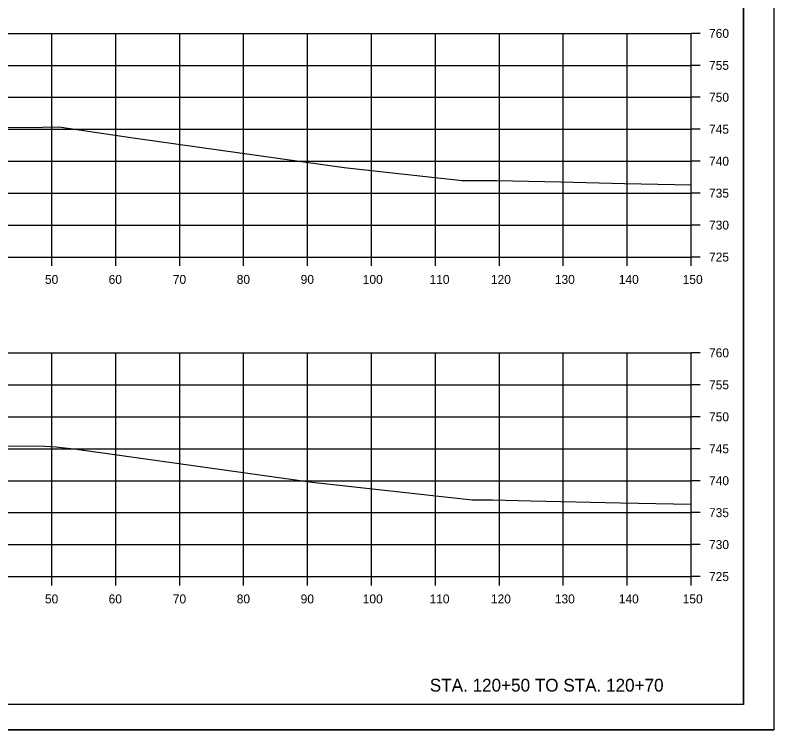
# Model space of a CAD drawing. Extents: x 1202951 to 1376887, y 378065 to 728038.
# Drawn here: x 1370161 to 1370279.6, y 380044.9 to 380156.7 of the extents above; entities that cross this region are included whole.
import ezdxf

# ---------------------------------------------------------------- set-up
doc = ezdxf.new("R2010")
doc.units = 0
for name, color, linetype in [('R_Axis', 7, 'Continuous'), ('R_Axis Annot', 7, 'Continuous'), ('R_Draft', 7, 'Continuous'), ('R_Exist Surface', 7, 'Continuous'), ('R_Grid', 7, 'Continuous'), ('R_No Plot', 7, 'Continuous')]:
    doc.layers.add(name, color=color, linetype=linetype)

msp = doc.modelspace()

# ---------------------------------------------------------------- linework, layer by layer
at = {"layer": 'R_Axis'}
for p, q in [((1370266.7, 380118.85), (1370266.7, 380153.85)), ((1370268.1, 380153.85), (1370266.7, 380153.85)), ((1370268.1, 380148.85), (1370266.7, 380148.85)), ((1370268.1, 380143.85), (1370266.7, 380143.85)), ((1370268.1, 380138.85), (1370266.7, 380138.85)), ((1370268.1, 380133.85), (1370266.7, 380133.85)), ((1370268.1, 380128.85), (1370266.7, 380128.85)), ((1370268.1, 380123.85), (1370266.7, 380123.85)), ((1369966.7, 380118.85), (1370266.7, 380118.85)), ((1370166.7, 380117.45), (1370166.7, 380118.85)), ((1370176.7, 380117.45), (1370176.7, 380118.85)), ((1370186.7, 380117.45), (1370186.7, 380118.85)), ((1370196.7, 380117.45), (1370196.7, 380118.85)), ((1370206.7, 380117.45), (1370206.7, 380118.85)), ((1370216.7, 380117.45), (1370216.7, 380118.85)), ((1370226.7, 380117.45), (1370226.7, 380118.85)), ((1370236.7, 380117.45), (1370236.7, 380118.85)), ((1370246.7, 380117.45), (1370246.7, 380118.85)), ((1370256.7, 380117.45), (1370256.7, 380118.85)), ((1370266.7, 380117.45), (1370266.7, 380118.85)), ((1370268.1, 380118.85), (1370266.7, 380118.85)), ((1370266.7, 380068.85), (1370266.7, 380103.85)), ((1370268.1, 380103.85), (1370266.7, 380103.85)), ((1370268.1, 380098.85), (1370266.7, 380098.85)), ((1370268.1, 380093.85), (1370266.7, 380093.85)), ((1370268.1, 380088.85), (1370266.7, 380088.85)), ((1370268.1, 380083.85), (1370266.7, 380083.85)), ((1370268.1, 380078.85), (1370266.7, 380078.85)), ((1370268.1, 380073.85), (1370266.7, 380073.85)), ((1369966.7, 380068.85), (1370266.7, 380068.85)), ((1370166.7, 380067.45), (1370166.7, 380068.85)), ((1370176.7, 380067.45), (1370176.7, 380068.85)), ((1370186.7, 380067.45), (1370186.7, 380068.85)), ((1370196.7, 380067.45), (1370196.7, 380068.85)), ((1370206.7, 380067.45), (1370206.7, 380068.85)), ((1370216.7, 380067.45), (1370216.7, 380068.85)), ((1370226.7, 380067.45), (1370226.7, 380068.85)), ((1370236.7, 380067.45), (1370236.7, 380068.85)), ((1370246.7, 380067.45), (1370246.7, 380068.85)), ((1370256.7, 380067.45), (1370256.7, 380068.85)), ((1370266.7, 380067.45), (1370266.7, 380068.85)), ((1370268.1, 380068.85), (1370266.7, 380068.85))]:
    msp.add_line(p, q, dxfattribs=at)
at = {"layer": 'R_Exist Surface'}
for points in [[(1370151.15, 380139.23), (1370162.7, 380139.13), (1370167.79, 380139.23), (1370179.43, 380137.52), (1370212.44, 380132.87), (1370230.88, 380130.84), (1370236.25, 380130.85), (1370246.31, 380130.6), (1370256.29, 380130.38), (1370266.7, 380130.16)], [(1370150.95, 380089.36), (1370165.61, 380089.23), (1370167.37, 380089.14), (1370168.19, 380089.06), (1370170.19, 380088.84), (1370207.44, 380083.61), (1370232.44, 380080.85), (1370235.63, 380080.86), (1370241.61, 380080.71), (1370255.66, 380080.4), (1370266.7, 380080.17)]]:
    msp.add_lwpolyline(points, dxfattribs=at)
at = {"layer": 'R_Grid'}
for p, q in [((1369966.7, 380153.85), (1370266.7, 380153.85)), ((1370166.7, 380118.85), (1370166.7, 380153.85)), ((1370176.7, 380118.85), (1370176.7, 380153.85)), ((1370186.7, 380118.85), (1370186.7, 380153.85)), ((1370196.7, 380118.85), (1370196.7, 380153.85)), ((1370206.7, 380118.85), (1370206.7, 380153.85)), ((1370216.7, 380118.85), (1370216.7, 380153.85)), ((1370226.7, 380118.85), (1370226.7, 380153.85)), ((1370236.7, 380118.85), (1370236.7, 380153.85)), ((1370246.7, 380118.85), (1370246.7, 380153.85)), ((1370256.7, 380118.85), (1370256.7, 380153.85)), ((1370266.7, 380118.85), (1370266.7, 380153.85)), ((1369966.7, 380148.85), (1370266.7, 380148.85)), ((1369966.7, 380143.85), (1370266.7, 380143.85)), ((1369966.7, 380138.85), (1370266.7, 380138.85)), ((1369966.7, 380133.85), (1370266.7, 380133.85)), ((1369966.7, 380128.85), (1370266.7, 380128.85)), ((1369966.7, 380123.85), (1370266.7, 380123.85)), ((1369966.7, 380118.85), (1370266.7, 380118.85)), ((1369966.7, 380103.85), (1370266.7, 380103.85)), ((1370166.7, 380068.85), (1370166.7, 380103.85)), ((1370176.7, 380068.85), (1370176.7, 380103.85)), ((1370186.7, 380068.85), (1370186.7, 380103.85)), ((1370196.7, 380068.85), (1370196.7, 380103.85)), ((1370206.7, 380068.85), (1370206.7, 380103.85)), ((1370216.7, 380068.85), (1370216.7, 380103.85)), ((1370226.7, 380068.85), (1370226.7, 380103.85)), ((1370236.7, 380068.85), (1370236.7, 380103.85)), ((1370246.7, 380068.85), (1370246.7, 380103.85)), ((1370256.7, 380068.85), (1370256.7, 380103.85)), ((1370266.7, 380068.85), (1370266.7, 380103.85)), ((1369966.7, 380098.85), (1370266.7, 380098.85)), ((1369966.7, 380093.85), (1370266.7, 380093.85)), ((1369966.7, 380088.85), (1370266.7, 380088.85)), ((1369966.7, 380083.85), (1370266.7, 380083.85)), ((1369966.7, 380078.85), (1370266.7, 380078.85)), ((1369966.7, 380073.85), (1370266.7, 380073.85)), ((1369966.7, 380068.85), (1370266.7, 380068.85))]:
    msp.add_line(p, q, dxfattribs=at)
at = {"layer": 'R_No Plot'}
for p, q in [((1370274.88, 380048.85), (1370274.88, 380254.31)), ((1370274.88, 380048.85), (1369958.7, 380048.85)), ((1369946.3, 380044.87), (1370279.63, 380044.87))]:
    msp.add_line(p, q, dxfattribs=at)
for points in [[(1369946.29, 380258.2), (1370279.63, 380258.2), (1370279.63, 380044.86), (1369946.29, 380044.86)], [(1370192.62, 380254.31), (1370212.24, 380254.31), (1370212.24, 380244.43), (1370228.35, 380244.43), (1370251.55, 380244.43), (1370251.55, 380220.09), (1370274.88, 380220.09), (1370274.88, 380048.85), (1369958.7, 380048.85), (1369958.7, 380254.31)]]:
    msp.add_lwpolyline(points, close=True, dxfattribs=at)

# ---------------------------------------------------------------- texts
at = {"layer": 'R_Axis Annot'}
for s, p in [('760', (1370269.5, 380153.15)), ('755', (1370269.5, 380148.15)), ('750', (1370269.5, 380143.15)), ('745', (1370269.5, 380138.15)), ('740', (1370269.5, 380133.15)), ('735', (1370269.5, 380128.15)), ('730', (1370269.5, 380123.15)), ('725', (1370269.5, 380118.15)), ('50', (1370165.62, 380114.65)), ('60', (1370175.58, 380114.65)), ('70', (1370185.62, 380114.65)), ('80', (1370195.62, 380114.65)), ('90', (1370205.62, 380114.65)), ('100', (1370215.33, 380114.65)), ('110', (1370225.78, 380114.65)), ('120', (1370235.38, 380114.65)), ('130', (1370245.38, 380114.65)), ('140', (1370255.38, 380114.65)), ('150', (1370265.38, 380114.65)), ('760', (1370269.5, 380103.15)), ('755', (1370269.5, 380098.15)), ('750', (1370269.5, 380093.15)), ('745', (1370269.5, 380088.15)), ('740', (1370269.5, 380083.15)), ('735', (1370269.5, 380078.15)), ('730', (1370269.5, 380073.15)), ('725', (1370269.5, 380068.15)), ('50', (1370165.62, 380064.65)), ('60', (1370175.58, 380064.65)), ('70', (1370185.62, 380064.65)), ('80', (1370195.62, 380064.65)), ('90', (1370205.62, 380064.65)), ('100', (1370215.33, 380064.65)), ('110', (1370225.78, 380064.65)), ('120', (1370235.38, 380064.65)), ('130', (1370245.38, 380064.65)), ('140', (1370255.38, 380064.65)), ('150', (1370265.38, 380064.65))]:
    msp.add_text(s, height=1.4, dxfattribs=at).set_placement(p)
at = {"layer": 'R_Draft'}
msp.add_text('STA. 120+50 TO STA. 120+70', height=2, dxfattribs=at).set_placement((1370225.82, 380050.85))

doc.saveas('drawing.dxf')
